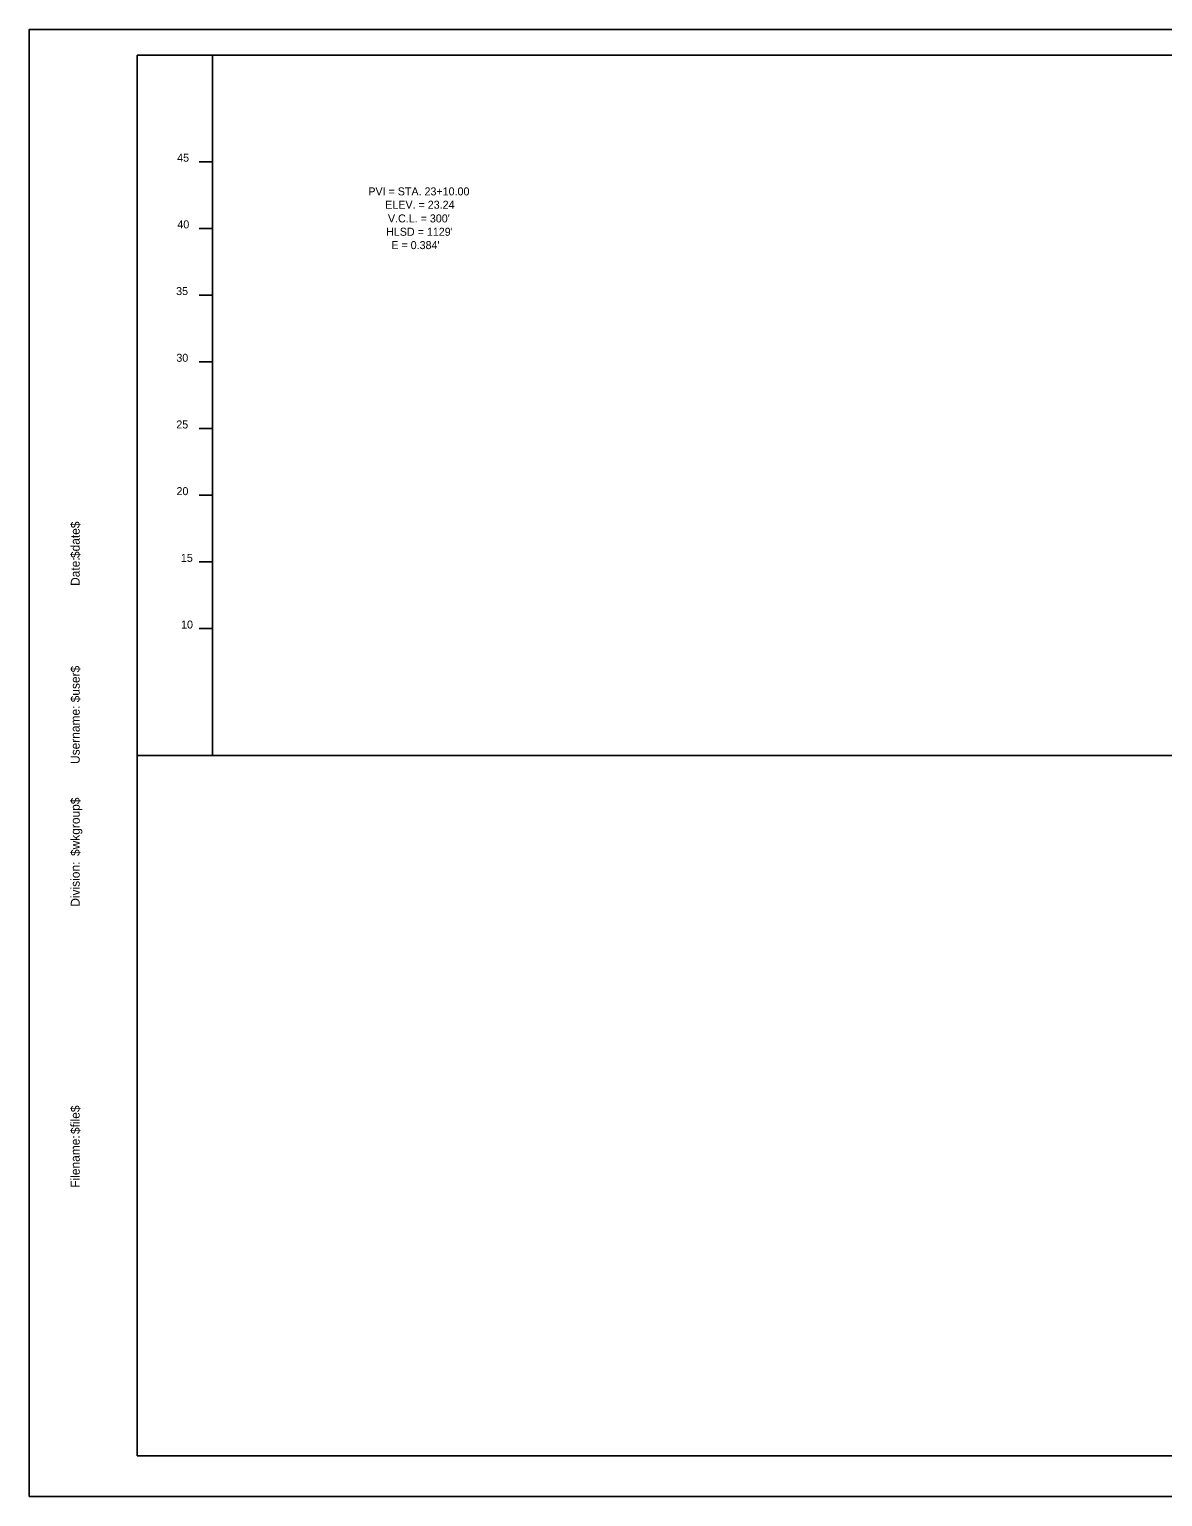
# Model space of a CAD drawing. Extents: x 0 to 850, y 0 to 550.
# Drawn here: x 0 to 425, y 0 to 550 of the extents above; entities that cross this region are included whole.
import ezdxf

# ---------------------------------------------------------------- set-up
doc = ezdxf.new("R2010")
doc.units = 0
for name, color, linetype in [('BORDER', 7, 'Continuous'), ('D_Roadway_Centerline_CurveData', 7, 'Continuous'), ('Default', 7, 'Continuous'), ('H_V ANNOTATION', 7, 'Continuous'), ('MAJOR', 7, 'Continuous'), ('PLOT BOUNDARY', 7, 'Continuous')]:
    doc.layers.add(name, color=color, linetype=linetype)

msp = doc.modelspace()

# ---------------------------------------------------------------- linework, layer by layer
at = {"layer": 'BORDER'}
for p, q in [((840.5, 540.32), (40.47, 540.32)), ((40.47, 540.32), (40.47, 15.3)), ((40.47, 15.3), (840.5, 15.3))]:
    msp.add_line(p, q, dxfattribs=at)
at = {"layer": 'Default'}
for points in [[(790.49, 277.83), (68.66, 277.83), (68.66, 540.32), (790.49, 540.32)], [(40.47, 15.3), (790.49, 15.3), (790.49, 277.83), (40.47, 277.83)]]:
    msp.add_lwpolyline(points, close=True, dxfattribs=at)
at = {"layer": 'MAJOR'}
for p, q in [((63.66, 500.42), (68.66, 500.42)), ((63.66, 500.42), (68.66, 500.42)), ((63.66, 475.42), (68.66, 475.42)), ((63.66, 450.42), (68.66, 450.42)), ((63.66, 425.42), (68.66, 425.42)), ((63.66, 400.42), (68.66, 400.42)), ((63.66, 375.42), (68.66, 375.42)), ((63.66, 350.42), (68.66, 350.42)), ((63.66, 325.42), (68.66, 325.42))]:
    msp.add_line(p, q, dxfattribs=at)
at = {"layer": 'PLOT BOUNDARY'}
msp.add_lwpolyline([(0, 0.01), (850.03, 0.01), (850.03, 550.02), (0, 550.02)], close=True, dxfattribs=at)

# ---------------------------------------------------------------- texts
at = {"layer": 'BORDER'}
for s, p in [('$date$', (18.9, 351.84)), ('Date:', (18.9, 341.4)), ('$user$', (18.9, 297.77)), ('Username:', (18.9, 274.65)), ('$wkgroup$', (18.9, 240.16)), ('Division:', (18.9, 221.14)), ('$file$', (18.9, 135.93)), ('Filename:', (18.9, 115.8))]:
    msp.add_text(s, height=3.348, rotation=90, dxfattribs=at).set_placement(p)
at = {"layer": 'D_Roadway_Centerline_CurveData'}
for s, p in [('PVI = STA. 23+10.00', (127.14, 487.78)), ('ELEV. = 23.24', (133.47, 482.78)), ("V.C.L. = 300'", (134.49, 477.65)), ("HLSD = 1129'", (133.81, 472.65)), ("E = 0.384'", (135.77, 467.65))]:
    msp.add_text(s, height=3, dxfattribs=at).set_placement(p)
at = {"layer": 'H_V ANNOTATION'}
for s, p in [('45', (55.44, 500.42)), ('45', (55.44, 500.42)), ('40', (55.52, 475.42)), ('35', (55.06, 450.42)), ('30', (55.14, 425.42)), ('25', (55.12, 400.42)), ('20', (55.2, 375.42)), ('15', (56.83, 350.42)), ('10', (56.91, 325.42))]:
    msp.add_text(s, height=3, dxfattribs=at).set_placement(p)

doc.saveas('drawing.dxf')
